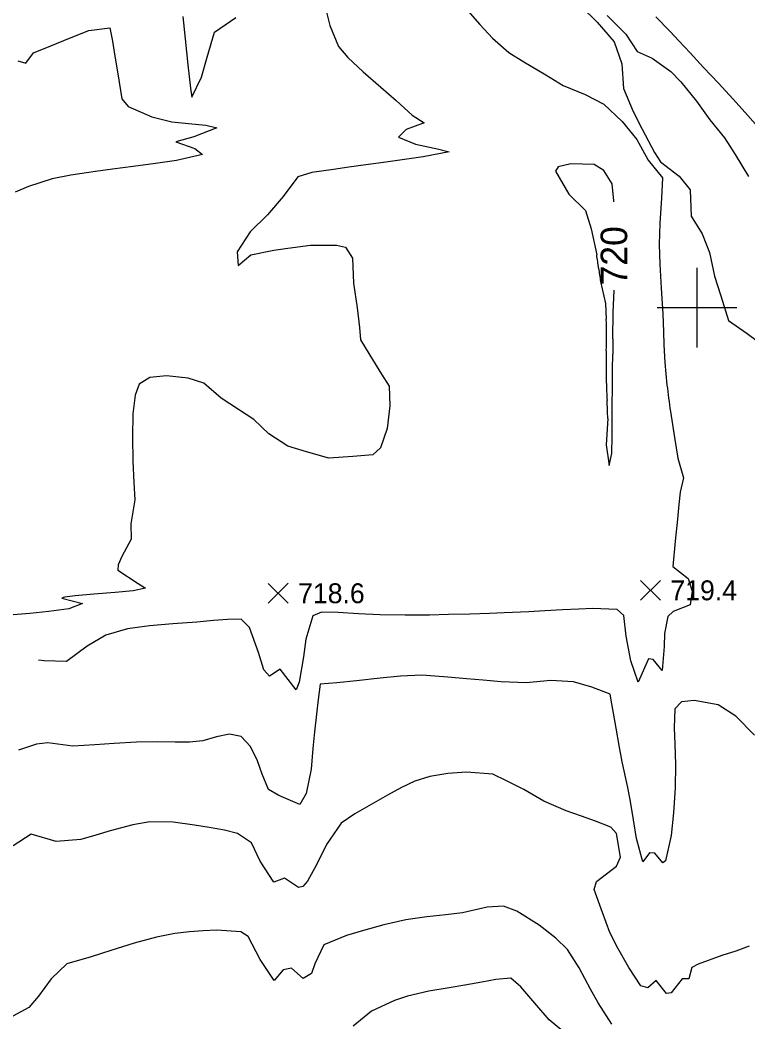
# Model space of a CAD drawing. Extents: x 2566079 to 2571326, y 424054 to 426896.
# Drawn here: x 2569490 to 2570038, y 424461 to 425217 of the extents above; entities that cross this region are included whole.
import ezdxf

# ---------------------------------------------------------------- set-up
doc = ezdxf.new("R2010")
doc.units = 0
for name, color, linetype in [('Contour_ADS_Label_Major', 7, 'Continuous'), ('Contour_ADS_Major', 7, 'Continuous'), ('Contour_ADS_Minor', 7, 'Continuous'), ('Contour_ADS_Spot_Elevation', 7, 'Continuous'), ('Contour_ADS_Tick', 7, 'Continuous')]:
    doc.layers.add(name, color=color, linetype=linetype)

# ---------------------------------------------------------------- blocks, each defined once
blk = doc.blocks.new('S890')
at = {"layer": 'Contour_ADS_Tick'}
for p, q in [((0, -0.5), (0, 0.5)), ((-0.5, 0), (0.5, 0))]:
    blk.add_line(p, q, dxfattribs=at)
blk = doc.blocks.new('S750')
at = {"layer": 'Contour_ADS_Spot_Elevation'}
for p, q in [((-0.5, 0.498), (0.5, -0.498)), ((-0.498, -0.5), (0.498, 0.5))]:
    blk.add_line(p, q, dxfattribs=at)

msp = doc.modelspace()

# ---------------------------------------------------------------- linework, layer by layer
at = {"layer": 'Contour_ADS_Major'}
for points in [[(2569825.49, 425225.71), (2569836.28, 425213.35), (2569845.68, 425203.17), (2569858.17, 425192.4), (2569869.42, 425185.34), (2569885.93, 425175.54), (2569899.08, 425167.45), (2569915.53, 425160.64), (2569929.67, 425153.23), (2569943.51, 425140.18), (2569954.63, 425126.67), (2569963.18, 425111.09), (2569973.83, 425097.76), (2569973.18, 425082.6), (2569971.94, 425063.59), (2569971.4, 425047.51), (2569971.99, 425032.71), (2569972.91, 425014.69), (2569974.13, 424995.29), (2569974.63, 424981.81), (2569974.93, 424971.91), (2569975.68, 424958.55), (2569977.27, 424941.62)], [(2569937.24, 425079.77), (2569937.2, 425080.42), (2569935.96, 425093.17), (2569929.69, 425103.29), (2569922.42, 425107.81), (2569904.71, 425108.27), (2569895.36, 425106.17), (2569893.27, 425102.87), (2569903.23, 425085.58), (2569915.92, 425073.24), (2569920.21, 425059.3), (2569924.33, 425039.78)], [(2569927.2, 425019.69), (2569931.02, 425003.04), (2569931.55, 424991.29)], [(2569936.49, 424976.53), (2569936.71, 424996.3), (2569937.38, 425013.11)], [(2569932.62, 424916.34), (2569931.55, 424896.53), (2569933.76, 424880.9), (2569935.8, 424889.98), (2569935.9, 424903.13), (2569935.99, 424914.7), (2569936.08, 424926.27), (2569936.19, 424939.84), (2569936.29, 424953.41), (2569936.39, 424964.97)], [(2569979.9, 424921.72), (2569982.91, 424902.06), (2569985.47, 424886.53), (2569989.67, 424871.55), (2569987.33, 424860.77), (2569986.31, 424851.48), (2569985.24, 424840.48), (2569983.43, 424823.79), (2569981.66, 424804.67), (2569993.28, 424795.67), (2569996.37, 424786.14), (2569994.76, 424775.8), (2569981.85, 424770.9), (2569978.02, 424767.19), (2569975.47, 424754.25), (2569975.07, 424744.54), (2569973.57, 424726.51), (2569966.82, 424734.61), (2569963.41, 424735.28), (2569955.64, 424717.57), (2569950.13, 424733.73), (2569946.49, 424752.29), (2569944.66, 424767.8), (2569939.68, 424772.41), (2569921.2, 424773.09), (2569910.95, 424772.65), (2569898.41, 424772.04), (2569885.15, 424771.36), (2569873.12, 424770.74), (2569854.46, 424769.83), (2569843.43, 424769.41), (2569828.8, 424768.94), (2569812.69, 424768.49), (2569798.19, 424768.18), (2569780.03, 424768.11), (2569760.87, 424768.4), (2569744.84, 424769.07), (2569729.47, 424770), (2569716.96, 424770.32), (2569710.32, 424767.58), (2569705.04, 424749.98), (2569703.35, 424736.8), (2569700, 424717.57), (2569697.73, 424711.91), (2569685.67, 424727.4), (2569677.68, 424722.09), (2569673.49, 424726.81), (2569669.31, 424740.06), (2569662.72, 424758.76), (2569656.46, 424765.13), (2569645.96, 424764.81), (2569635.42, 424763.96), (2569623.04, 424762.93), (2569604.87, 424761.48), (2569587.29, 424759.95), (2569570.72, 424757.86), (2569554.42, 424753.15), (2569540.21, 424744.75), (2569524.77, 424733.09), (2569507.88, 424733.77), (2569503.66, 424734.06)]]:
    msp.add_lwpolyline(points, dxfattribs=at)
for centre, radius, start, end in [((2569622, 424991.3), 306.19, 7.21303, 9.11108), ((2570148.84, 425056.35), 224.65, 186.80357, 189.39277), ((2569267.07, 424979.38), 664.58, 358.97271, 1.02729), ((2576688.78, 424912.34), 6752.59, 179.455328, 179.553419), ((2570887.68, 424955.55), 956.2, 179.28633, 180.71367), ((2570887.42, 424973.92), 956.35, 181.81435, 182.63276), ((2570692.94, 425026.08), 720.64, 186.73062, 188.32663), ((2569679.69, 424913.17), 252.95, 0.71811, 3.81281)]:
    msp.add_arc(centre, radius, start, end, dxfattribs=at)
at = {"layer": 'Contour_ADS_Minor'}
for points in [[(2569912.19, 425227.49), (2569924.77, 425215.17), (2569937.49, 425200.41), (2569943.2, 425183.7), (2569944.48, 425165.27), (2569951.69, 425147.75), (2569958.47, 425134.43), (2569967.92, 425116.96), (2569972.35, 425109.93), (2569986.34, 425099.09), (2569994.76, 425088.7), (2569995.39, 425068.95), (2570003.79, 425055.58), (2570009.22, 425041.45), (2570013.15, 425023.7), (2570017.96, 425008.79), (2570023.64, 424990.17), (2570037.74, 424980.42), (2570052.26, 424969.68)], [(2569720.38, 425223.7), (2569723.26, 425212.59), (2569729.68, 425196.77), (2569736.78, 425188.48), (2569748.22, 425177.76), (2569761.51, 425166.17), (2569773.24, 425156.04), (2569785.3, 425145.04), (2569794.24, 425139.34), (2569780.83, 425134.12), (2569774.98, 425128.5), (2569787.87, 425123.22), (2569805.21, 425119.54), (2569813.02, 425117.42), (2569793.55, 425113.56), (2569775.91, 425111.02), (2569763.51, 425109.36), (2569750.3, 425107.57), (2569737.47, 425105.79), (2569725.93, 425104.14), (2569709.69, 425101.76), (2569699.17, 425098.45), (2569688.12, 425083.68), (2569676.22, 425069.91), (2569663.15, 425057.08), (2569653.31, 425041.94), (2569654.07, 425031.6), (2569663.73, 425039.86), (2569681.1, 425043.22), (2569691.57, 425044.79), (2569708.52, 425047.01), (2569728.15, 425046.99), (2569734.87, 425045.46), (2569740.29, 425037.16), (2569741.1, 425018.51), (2569743.72, 424999.77), (2569745.49, 424984.92), (2569746.42, 424975.64), (2569753.24, 424964.15), (2569762.07, 424949.8), (2569767.84, 424940.7), (2569768.47, 424925.8), (2569766.46, 424908.93), (2569761.29, 424894.34), (2569755.5, 424888.98), (2569740.59, 424887.71), (2569722.47, 424886.36), (2569705.71, 424891.18), (2569691.66, 424895.63), (2569677.23, 424904.78), (2569665.94, 424915.68), (2569654.33, 424923.07), (2569641.22, 424931.72), (2569628.31, 424943.03), (2569616.48, 424946.82), (2569600.18, 424948.47), (2569587.49, 424947.34), (2569579.56, 424942.3), (2569576.42, 424934.05), (2569574.75, 424919.97), (2569574.35, 424902.28), (2569574.78, 424884.1), (2569575.6, 424868.1), (2569576.22, 424855.17), (2569573.11, 424836.84), (2569573.43, 424825.34), (2569566.5, 424812.22), (2569563.65, 424806.15), (2569563.51, 424801.98), (2569578.84, 424792.04), (2569584.26, 424788.49), (2569575.06, 424786.4), (2569561.48, 424785.18), (2569545.31, 424783.86), (2569531.27, 424782.66), (2569523.18, 424781.7), (2569521.12, 424780.84)], [(2569612.28, 425219.54), (2569614.07, 425202.56), (2569616.24, 425183.1), (2569618.19, 425165.45), (2569619.31, 425158.71), (2569626.35, 425173.69), (2569630.65, 425188.78), (2569636.3, 425207.53), (2569652.25, 425218.56)], [(2569932.31, 425220.19), (2569946.14, 425206.23), (2569954.78, 425192.97), (2569966.1, 425187.91), (2569980.28, 425178), (2569987.83, 425170.29), (2569999.47, 425155.67), (2570009.47, 425141.61), (2570020.62, 425127.95), (2570028.75, 425115.47), (2570038.62, 425098.84)], [(2569968.98, 425219.14), (2569979.4, 425208.36), (2569986.18, 425201.2), (2569994.63, 425192.16), (2570004.91, 425181.1), (2570016.05, 425169.05), (2570026.81, 425157.34), (2570036.18, 425147.07), (2570044.06, 425138.34), (2570056.07, 425124.81), (2570068.57, 425110.94), (2570077.66, 425101.2), (2570087.46, 425090.77), (2570095.99, 425081.64)], [(2569488.05, 425186.03), (2569494.18, 425184.27), (2569499.97, 425192.13), (2569512.96, 425197.36), (2569527.08, 425203.2), (2569541.48, 425208.83), (2569557.27, 425210.95), (2569559.37, 425200.89), (2569561.21, 425189.52), (2569563.38, 425176.14), (2569566.51, 425157.44), (2569571.32, 425151.55), (2569589.03, 425143.87), (2569604.08, 425139.97), (2569616.57, 425138.84), (2569629.82, 425137.43), (2569638.02, 425135.62), (2569620.78, 425128.76), (2569607.2, 425125.05), (2569621.51, 425120.04), (2569627.12, 425115.38), (2569607.73, 425110.76), (2569591.87, 425108.51), (2569575.08, 425106.29), (2569559.33, 425104.26), (2569546.47, 425102.61), (2569527.97, 425099.74), (2569513.87, 425097.06), (2569496.09, 425091.32), (2569485.98, 425087.08)], [(2569521.12, 424780.84), (2569536.74, 424776.93), (2569526.61, 424772.9), (2569511.47, 424770.89), (2569497.01, 424769.36), (2569481.64, 424768.19)], [(2569959.01, 424582.21), (2569954.33, 424599.83), (2569952.07, 424613.92), (2569949.79, 424627.56), (2569947.71, 424638.26), (2569943.55, 424657.42), (2569941.19, 424669.82), (2569938.88, 424682.86), (2569935.8, 424701.29), (2569934.41, 424708.65), (2569920.56, 424713.82), (2569906.85, 424717.86), (2569889.75, 424718.83), (2569871.17, 424717.04), (2569852.26, 424717.85), (2569838.72, 424719.05), (2569826.16, 424720.13), (2569812.13, 424721.32), (2569792.42, 424722.9), (2569776.4, 424722.06), (2569761.06, 424720.49), (2569743.39, 424718.63), (2569728.45, 424717.06), (2569715.88, 424716.16), (2569714.35, 424704.49), (2569713.1, 424693.42), (2569711.66, 424680.11), (2569710.41, 424667.67), (2569709.13, 424652.07), (2569705.33, 424633.67), (2569700.58, 424625.32), (2569684.75, 424632.2), (2569676.98, 424636.57), (2569672.12, 424648.23), (2569668.56, 424658.18), (2569663.39, 424669.01), (2569656.42, 424676.7), (2569647.66, 424678.47), (2569637.76, 424676.31), (2569627.55, 424673.41), (2569617.48, 424672.25), (2569606.55, 424672.39), (2569593.4, 424672.7), (2569577.38, 424672.31), (2569560.64, 424671.4), (2569546.09, 424670.42), (2569529.38, 424669.45), (2569510.55, 424671.87), (2569502.06, 424670.91), (2569488.49, 424666.36)], [(2570043.15, 424677.69), (2570029.29, 424691.95), (2570015.83, 424700.62), (2569997.8, 424703.65), (2569988.13, 424702.69), (2569983.16, 424697.57), (2569982.6, 424683.22), (2569983.15, 424670.85), (2569983.6, 424655.44), (2569983.42, 424637.82), (2569982.23, 424619.2), (2569980.31, 424602.06), (2569976.05, 424582.79), (2569974.09, 424581.44), (2569968.24, 424588.7), (2569964.09, 424589.04), (2569959.01, 424582.21)], [(2570039.12, 424518.55), (2570029.04, 424514.75), (2570018.7, 424511.41), (2570000.74, 424505.07), (2569996.01, 424502.45), (2569993.7, 424494.05), (2569988.7, 424493.88), (2569980.36, 424483.45), (2569976.82, 424482.82), (2569969.07, 424492.76), (2569962.82, 424487.26), (2569957.48, 424488.78), (2569948.5, 424502.51), (2569940.15, 424517.02), (2569934.12, 424528.95), (2569928.76, 424544), (2569922.49, 424561.36), (2569924.04, 424567.33), (2569939.24, 424579), (2569942.12, 424585.7), (2569939.26, 424603.6), (2569935.01, 424608.21), (2569923.41, 424612.88), (2569912.9, 424616.5), (2569901.22, 424620.63), (2569884.46, 424627.86), (2569869.51, 424636.63), (2569856.41, 424643.12), (2569845.94, 424648.27), (2569826.09, 424649.76), (2569812.07, 424648.69), (2569798.49, 424646.39), (2569787.22, 424642.88), (2569777.19, 424638.18), (2569766.58, 424632.33), (2569754.27, 424625.48), (2569741.92, 424618.23), (2569731.83, 424611.29), (2569720.61, 424595.24), (2569713.31, 424580.4), (2569706.32, 424567.67), (2569702.74, 424563.61), (2569699.47, 424562.86), (2569689.08, 424569.74), (2569680.99, 424566.81), (2569670.74, 424582.58), (2569664.25, 424596.48), (2569653.63, 424603.52), (2569643.78, 424605.97), (2569632.21, 424608.04), (2569621.12, 424609.74), (2569605.13, 424612), (2569587.53, 424612.19), (2569574.69, 424610.14), (2569557.69, 424605.62), (2569546.81, 424602.18), (2569535.45, 424598.94), (2569516.91, 424597.35), (2569498.08, 424603), (2569484.43, 424594.29)], [(2569935.59, 424459.79), (2569925.4, 424475.82), (2569919.58, 424486.27), (2569911, 424502.16), (2569902.34, 424516.02), (2569893.49, 424524.56), (2569880.95, 424534.37), (2569864.11, 424544.84), (2569854.19, 424548.83), (2569841.82, 424547.95), (2569823.26, 424543.82), (2569810.72, 424542.25), (2569796.28, 424540.69), (2569780.45, 424538.32), (2569763.98, 424534.64), (2569748.47, 424530.37), (2569735.79, 424526.51), (2569718.77, 424519.66), (2569711.84, 424505.37), (2569709.26, 424497.99), (2569702.97, 424494.16), (2569694.32, 424501.86), (2569687.91, 424500.84), (2569681.27, 424492.77), (2569670.81, 424508.55), (2569661.74, 424525.76), (2569656.19, 424529.36)], [(2569656.19, 424529.36), (2569638.1, 424530.73), (2569627.65, 424530.05), (2569617.41, 424529.39), (2569606.28, 424528.15), (2569592.67, 424525.46), (2569575.81, 424520.82), (2569558.24, 424515.35), (2569543.32, 424510.53), (2569525.07, 424505.15), (2569513.17, 424493.92), (2569503.66, 424480.88), (2569496.46, 424472.44), (2569484.39, 424465.86)], [(2569903.24, 424450.72), (2569888.56, 424462.92), (2569877.72, 424475.61), (2569867.04, 424487.88), (2569859.5, 424494.37), (2569848.37, 424493.32), (2569837.7, 424491.43), (2569824.94, 424489.19), (2569813.15, 424487.2), (2569797.72, 424484.75), (2569781.76, 424480.81), (2569771.87, 424477.57), (2569754.53, 424469.45), (2569740.78, 424458.29)]]:
    msp.add_lwpolyline(points, dxfattribs=at)

# ---------------------------------------------------------------- block references
at = {"layer": 'Contour_ADS_Spot_Elevation', "xscale": 15, "yscale": 15}
for p in [(2569964.84, 424786.83), (2569684.27, 424784.62)]:
    msp.add_blockref('S750', p, dxfattribs=at)
at = {"layer": 'Contour_ADS_Tick', "xscale": 60, "yscale": 60}
msp.add_blockref('S890', (2570000, 425000), dxfattribs=at)

# ---------------------------------------------------------------- texts
at = {"layer": 'Contour_ADS_Label_Major'}
msp.add_text('720', height=20, rotation=90.12505, dxfattribs=at).set_placement((2569947.37, 425016.73))
at = {"layer": 'Contour_ADS_Spot_Elevation'}
for s, p in [('719.4', (2569979.84, 424779.33)), ('718.6', (2569699.27, 424777.12))]:
    msp.add_text(s, height=15, dxfattribs=at).set_placement(p)

doc.saveas('drawing.dxf')
